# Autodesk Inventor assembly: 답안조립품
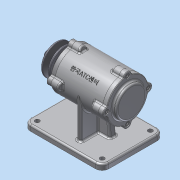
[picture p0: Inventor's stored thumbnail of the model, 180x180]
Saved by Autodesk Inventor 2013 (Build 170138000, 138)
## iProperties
Created: 2015-12
Part Number: 답안조립품
Document SubType Name: Assembly
Designer: dgall
Author: dgall
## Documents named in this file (11)
- C:\Users\dgall\Desktop\새 폴더\답안조립품.iam
- C:\Users\dgall\Desktop\새 폴더\본체.ipt
- C:\Users\dgall\Desktop\새 폴더\V-벨트풀리.ipt
- C:\Users\dgall\Desktop\새 폴더\너트 M12x1.25.ipt
- C:\Users\dgall\Desktop\새 폴더\베어링 6204.ipt
- C:\Users\dgall\Desktop\새 폴더\볼트 M4 x 12.ipt
- C:\Users\dgall\Desktop\새 폴더\오일실.ipt
- C:\Users\dgall\Desktop\새 폴더\축.ipt
- C:\Users\dgall\Desktop\새 폴더\커버.ipt
- C:\Users\dgall\Desktop\새 폴더\커버2.ipt
- C:\Users\dgall\Desktop\새 폴더\키(4 x 4 x 12).ipt
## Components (6 placed, 5 different names)
1. V-벨트풀리:1
2. KS B 1012 클래스 1 일반 - 미터 M12x1.25:1
3. KS B 2023 6204 - 20 x 47 x 14:1
4. KS B 2804 D D - 20 32 8:1
5. KS B 1311 (I) 4 x 4 x 12:1
6. KS B 2023 6204 - 20 x 47 x 14:2
